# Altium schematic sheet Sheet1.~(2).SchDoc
size A; SheetNumber: 1; SheetTotal: 1
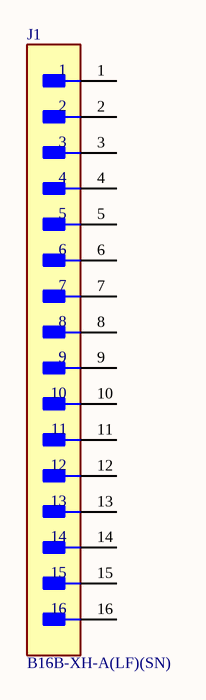
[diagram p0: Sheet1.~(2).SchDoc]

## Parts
J1  B16B-XH-A(LF)(SN)  [FP-B16B-XH-A_LF_SN-MFG]

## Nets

Not connected (* = marked no-connect by the designer): J1 1 2 3 4 5 6 7 8 9 10 11 12 13 14 15 16

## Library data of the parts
J1 = CMP-17439-000590-1: CONN HEADER VERT 16POS 2.5MM; Contact Resistance: 20mR; Number of Contacts: 16; Gender: Male; Pitch: 0.098inch; Connector Type: Male Pin; Max Voltage Rating (AC): 250V; Max Current Rating: 3A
